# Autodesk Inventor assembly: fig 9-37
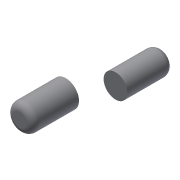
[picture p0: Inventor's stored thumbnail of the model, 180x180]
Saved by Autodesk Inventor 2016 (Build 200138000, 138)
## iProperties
Created: 2013-07
Part Number: fig 9-37
Document SubType Name: Assembly
Designer: CADCIM
Author: CADCIM
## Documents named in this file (3)
- D:\KAVITA\Autodesk Inventor_ 2016 Project_Kavita\Inventor_Part Files\Inventor_2016_Part\c09_Inv_2016\c09_inv_2016_prt\fig 9-37.iam
- D:\KAVITA\Autodesk Inventor_ 2016 Project_Kavita\Inventor_Part Files\Inventor_2016_Part\c09_Inv_2016\c09_inv_2016_prt\10.ipt
- D:\KAVITA\Autodesk Inventor_ 2016 Project_Kavita\Inventor_Part Files\Inventor_2016_Part\c09_Inv_2016\c09_inv_2016_prt\11.ipt
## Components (2 placed, 2 different names)
1. 10:1
2. 11:1
